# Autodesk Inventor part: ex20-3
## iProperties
Created: 2006-04
Part Number: ex20-3
Document SubType Name: Modeling
Designer: E. MOSS
Project: EVERGREEN VALLEY COLLEGE
Description: PLATE
Authority: MS. TEACHER
Author: E. MOSS
Revision Number: A
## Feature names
1. Extrusion1
2. Hole1
3. Extrusion2
